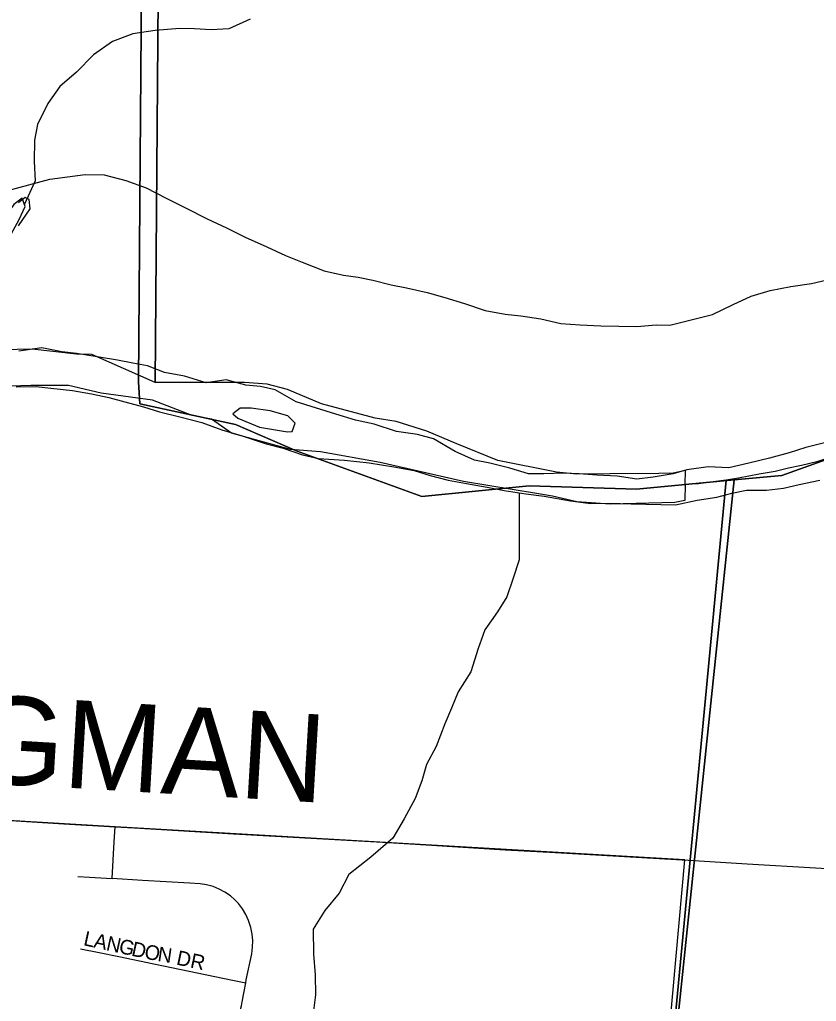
# Model space of a CAD drawing. Extents: x 0 to 1391, y -24 to 440.
# Drawn here: x 561.71 to 572, y 293.52 to 306.2 of the extents above; entities that cross this region are included whole.
import ezdxf

# ---------------------------------------------------------------- set-up
doc = ezdxf.new("R2010")
doc.units = 0
for name, color, linetype in [('GM_X_City_Street', 7, 'Continuous'), ('GM_X_City_Street_Text', 7, 'Continuous'), ('GM_X_Corporation', 7, 'Continuous'), ('GM_X_County_Road', 7, 'Continuous'), ('GM_X_County_Road_Text', 7, 'Continuous'), ('GM_X_Major_River', 7, 'Continuous'), ('GM_X_Minor_River', 7, 'Continuous'), ('GM_X_Section', 7, 'Continuous'), ('GM_X_Township', 7, 'Continuous')]:
    doc.layers.add(name, color=color, linetype=linetype)

msp = doc.modelspace()

# ---------------------------------------------------------------- linework, layer by layer
at = {"layer": 'GM_X_City_Street'}
for points in [[(562.907, 295.11), (562.934, 295.584), (562.937, 295.646), (562.944, 295.777)], [(562.463, 295.135), (562.613, 295.127), (562.907, 295.11)], [(564.632, 293.759), (564.639, 293.798), (564.711, 294.137), (564.721, 294.222), (564.722, 294.307), (564.714, 294.391), (564.697, 294.474), (564.667, 294.567), (564.633, 294.644), (564.589, 294.717), (564.538, 294.785), (564.488, 294.837), (564.433, 294.884), (564.362, 294.932), (564.288, 294.971), (564.209, 295.003), (564.127, 295.026), (564.043, 295.04), (563.908, 295.05), (563.3, 295.082), (562.907, 295.11)], [(562.495, 294.201), (562.739, 294.153), (562.993, 294.099), (563.443, 294.008), (564.461, 293.795), (564.632, 293.759)], [(564.013, 292.603), (564.042, 292.626), (564.191, 292.736), (564.265, 292.801), (564.323, 292.862), (564.375, 292.929), (564.42, 293.002), (564.467, 293.101), (564.506, 293.203), (564.54, 293.321), (564.576, 293.464), (564.586, 293.514), (564.612, 293.648), (564.632, 293.759)]]:
    msp.add_lwpolyline(points, dxfattribs=at)
at = {"layer": 'GM_X_Corporation'}
msp.add_lwpolyline([(569.105, 282), (570.303, 295.349), (562.944, 295.777), (556.772, 296.142), (556.024, 293.373)], dxfattribs=at)
at = {"layer": 'GM_X_County_Road'}
for points in [[(556.772, 296.142), (557.869, 296.08), (558.6, 296.037), (560.532, 295.917), (561.102, 295.885), (561.66, 295.854), (562.28, 295.814), (562.944, 295.777)], [(562.944, 295.777), (563.185, 295.764), (564.475, 295.687), (565.628, 295.622), (566.398, 295.577), (567.03, 295.537), (567.985, 295.478), (568.555, 295.448), (570.419, 295.342)], [(570.419, 295.342), (571.112, 295.298), (571.993, 295.245), (572.501, 295.216), (573.978, 295.126), (574.991, 295.065), (577.066, 294.941), (577.854, 294.895), (579.029, 294.826)]]:
    msp.add_lwpolyline(points, dxfattribs=at)
at = {"layer": 'GM_X_Major_River'}
for p, q in [((564.559, 301.183), (564.467, 301.108)), ((565.23, 300.883), (565.272, 300.991))]:
    msp.add_line(p, q, dxfattribs=at)
for points in [[(561.257, 301.993), (561.292, 302.092), (561.399, 302.22), (561.492, 302.371), (561.517, 302.492), (561.451, 302.713), (561.439, 303.032), (561.549, 303.335), (561.704, 303.621), (561.782, 303.788), (561.745, 303.894), (561.637, 303.812), (561.468, 303.571), (561.336, 303.322), (561.256, 303.05), (561.277, 302.822), (561.327, 302.563), (561.302, 302.358), (561.141, 302.208), (560.853, 302.102)], [(570.155, 300.334), (569.896, 300.292), (569.683, 300.264), (569.432, 300.306), (569.166, 300.317), (568.938, 300.335), (568.748, 300.345), (568.482, 300.333), (568.284, 300.336), (568.042, 300.408), (567.784, 300.472), (567.587, 300.512), (567.337, 300.622), (567.057, 300.785), (566.853, 300.841), (566.579, 300.883), (566.291, 300.978), (566.048, 301.026), (565.798, 301.106), (565.283, 301.264), (565.011, 301.42), (564.821, 301.461), (564.631, 301.478), (564.381, 301.55), (564.122, 301.508), (563.842, 301.595), (563.583, 301.644), (563.364, 301.73), (563.174, 301.763), (562.977, 301.804), (562.711, 301.845), (562.445, 301.887), (562.255, 301.912), (561.997, 301.961), (561.7, 301.92)], [(561.665, 301.457), (561.923, 301.461), (562.113, 301.443), (562.394, 301.409), (562.637, 301.368), (562.865, 301.319), (563.07, 301.263), (563.312, 301.199), (563.517, 301.136), (563.782, 301.072), (564.063, 300.999), (564.321, 300.905), (564.586, 300.825), (564.897, 300.723), (565.117, 300.666), (565.367, 300.58), (565.571, 300.531), (565.906, 300.512), (566.225, 300.477), (566.544, 300.427), (566.809, 300.378), (567.014, 300.315), (567.249, 300.251), (567.484, 300.21), (567.75, 300.161), (567.97, 300.12), (568.251, 300.078), (568.486, 300.045), (568.828, 299.987), (569.086, 299.953), (569.337, 299.957), (569.611, 299.946), (570.183, 299.934)], [(565.272, 300.991), (565.174, 301.084), (564.947, 301.147), (564.704, 301.181), (564.559, 301.183)], [(564.467, 301.108), (564.528, 301.054), (564.808, 300.936), (565.172, 300.878), (565.23, 300.883)], [(572.128, 300.739), (571.868, 300.677), (571.653, 300.606), (571.4, 300.536), (571.133, 300.474), (570.872, 300.412), (570.606, 300.427), (570.332, 300.388), (570.155, 300.334)], [(570.183, 299.934), (570.466, 299.996), (570.718, 300.035), (570.91, 300.084), (571.101, 300.124), (571.36, 300.126), (571.581, 300.151), (571.78, 300.199), (572.048, 300.253)]]:
    msp.add_lwpolyline(points, dxfattribs=at)
at = {"layer": 'GM_X_Minor_River'}
for points in [[(564.688, 306.207), (564.413, 306.082), (564.184, 306.071), (563.972, 306.082), (563.781, 306.085), (563.462, 306.06), (563.172, 306.019), (562.912, 305.917), (562.667, 305.746), (562.444, 305.522), (562.228, 305.336), (562.074, 305.118), (561.941, 304.847), (561.901, 304.643), (561.898, 304.37), (561.91, 304.119), (561.772, 303.817)], [(562.1, 304.139), (562.557, 304.2), (562.801, 304.196), (563.081, 304.123), (563.346, 304.028), (563.604, 303.894), (563.853, 303.769), (564.133, 303.628), (564.382, 303.51), (564.624, 303.392), (564.904, 303.266), (565.147, 303.156), (565.359, 303.069), (565.646, 302.958), (565.897, 302.9), (566.086, 302.875), (566.276, 302.834), (566.511, 302.777), (566.709, 302.735), (566.974, 302.678), (567.202, 302.613), (567.459, 302.533), (567.724, 302.446), (567.982, 302.396), (568.188, 302.377), (568.446, 302.335), (568.704, 302.278), (568.954, 302.259), (569.22, 302.247), (569.684, 302.239), (569.936, 302.258), (570.113, 302.255)], [(552.667, 300.673), (553.587, 301.545), (554.392, 301.998), (555.407, 302.337), (562.1, 304.139)], [(570.113, 302.255), (570.664, 302.392), (570.931, 302.521), (571.163, 302.631), (571.408, 302.701), (571.676, 302.755), (571.943, 302.794), (572.218, 302.856)], [(568.163, 300.091), (568.166, 299.222), (568.087, 298.988), (568.007, 298.747), (567.883, 298.552), (567.721, 298.319), (567.634, 298.078), (567.539, 297.776), (567.376, 297.521), (567.29, 297.31), (567.203, 297.106), (567.093, 296.812), (566.969, 296.579), (566.905, 296.368), (566.819, 296.141), (566.678, 295.878), (566.531, 295.63), (566.246, 295.385), (565.962, 295.162), (565.837, 294.921), (565.652, 294.697), (565.504, 294.456), (565.508, 294.13), (565.527, 293.864), (565.531, 293.606), (565.505, 293.364)]]:
    msp.add_lwpolyline(points, dxfattribs=at)
at = {"layer": 'GM_X_Section'}
for points in [[(563.567, 314.776), (563.463, 301.514), (562.644, 301.878), (562.447, 301.882), (561.872, 301.945), (561.486, 301.938)], [(572.01, 300.491), (571.812, 300.441), (571.645, 300.406), (571.47, 300.364), (571.265, 300.33), (570.999, 300.281), (570.84, 300.254), (570.635, 300.227), (570.483, 300.207), (570.309, 300.195), (570.312, 300.378), (570.152, 300.344), (569.97, 300.339), (569.334, 300.336), (568.91, 300.329), (568.645, 300.357), (567.89, 300.507), (567.357, 300.722), (566.973, 300.888), (566.574, 301.009), (566.302, 301.052), (565.609, 301.239), (565.173, 301.422), (564.909, 301.495), (564.614, 301.515), (563.463, 301.514), (563.567, 314.776)], [(561.698, 303.539), (561.846, 303.756), (561.833, 303.878), (561.78, 303.902), (561.696, 303.835)], [(569.108, 282), (570.84, 300.254), (570.635, 300.227), (570.483, 300.207), (570.309, 300.195), (570.305, 299.992), (570.176, 299.964), (569.342, 299.942), (568.911, 299.973), (568.594, 300.047), (568.39, 300.081), (567.446, 300.235), (566.367, 300.483), (565.597, 300.618), (565.211, 300.648), (564.45, 300.859), (564.189, 301.039), (563.94, 301.089), (563.428, 301.288), (562.763, 301.376), (562.341, 301.475), (561.856, 301.476), (561.598, 301.466)], [(586.54, 282), (588.094, 299.319), (572.742, 300.774), (572.582, 300.708), (572.468, 300.657), (572.193, 300.548), (572.01, 300.491), (571.812, 300.441), (571.645, 300.406), (571.47, 300.364), (571.265, 300.33), (570.999, 300.281), (570.84, 300.254), (569.108, 282)]]:
    msp.add_lwpolyline(points, dxfattribs=at)
at = {"layer": 'GM_X_Township'}
for points in [[(563.752, 363.742), (563.749, 363.357), (563.677, 355.031), (563.576, 343.168), (563.505, 334.791), (563.436, 326.438), (563.346, 314.735), (563.335, 313.31), (563.269, 304.402), (563.248, 301.521), (563.262, 301.241), (564.499, 300.973), (565.297, 300.626), (566.907, 300.044), (568.293, 300.179), (569.679, 300.135), (570.942, 300.256), (571.556, 300.315), (573.626, 301.053)], [(569.034, 282), (570.417, 295.228), (570.942, 300.256), (569.679, 300.135), (568.293, 300.179), (566.907, 300.044), (565.297, 300.626), (564.499, 300.973), (563.262, 301.241), (563.248, 301.521), (563.269, 304.402), (563.335, 313.31), (563.346, 314.735), (558.142, 314.749), (551.45, 314.755), (543.525, 314.752), (542.014, 314.776), (540.688, 314.776), (538.532, 314.775), (531.927, 314.772), (521.022, 314.955)], [(573.626, 301.053), (571.556, 300.315), (570.942, 300.256), (570.417, 295.228), (569.034, 282)]]:
    msp.add_lwpolyline(points, dxfattribs=at)

# ---------------------------------------------------------------- texts
at = {"layer": 'GM_X_City_Street_Text'}
for s, height, rotation, p in [('L', 0.189, 347.7201, (562.526, 294.248)), ('A', 0.189, 347.7083, (562.657, 294.22)), ('N', 0.189, 347.7083, (562.819, 294.184)), ('G', 0.189, 347.7083, (562.982, 294.149)), ('D', 0.189, 347.7083, (563.145, 294.113)), ('O', 0.189, 348.8723, (563.312, 294.077)), ('N', 0.189, 351.5568, (563.485, 294.043)), ('DR', 0.1894, 348.116, (563.726, 293.998))]:
    msp.add_text(s, height=height, rotation=rotation, dxfattribs=at).set_placement(p)
at = {"layer": 'GM_X_County_Road_Text'}
msp.add_text('DINGMAN', height=1.1364, rotation=356.6085, dxfattribs=at).set_placement((558.465, 296.51))

doc.saveas('drawing.dxf')
